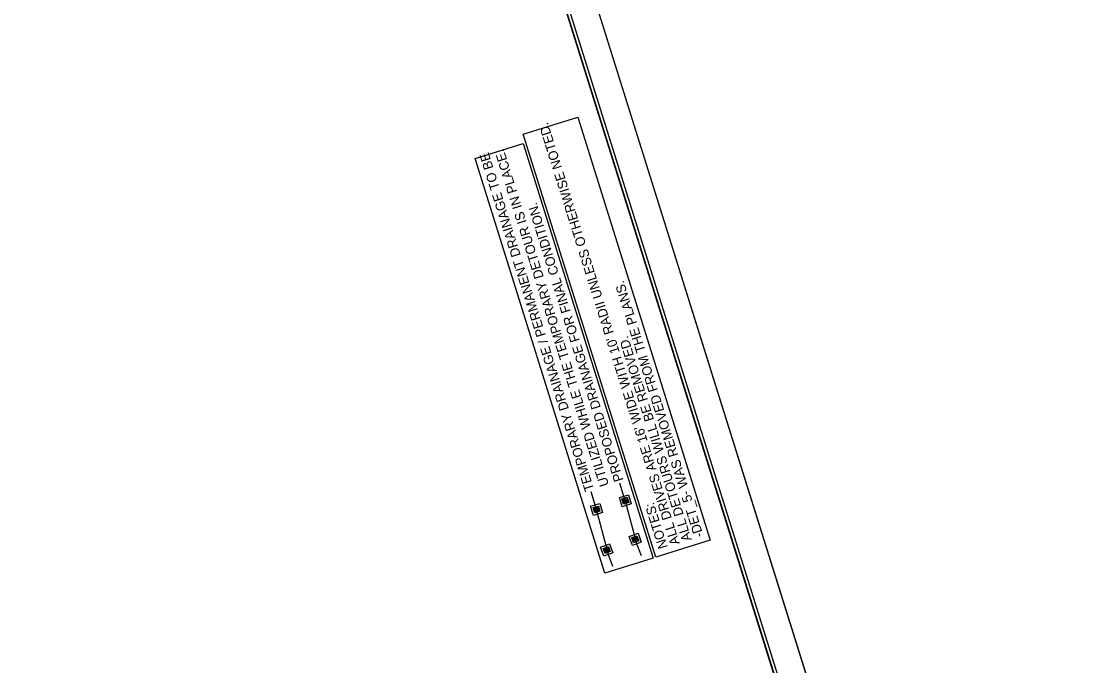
# Model space of a CAD drawing. Extents: x 473667 to 478950, y 494687 to 505998.
# Drawn here: x 474441 to 475215, y 505031 to 505503 of the extents above; entities that cross this region are included whole.
import ezdxf

# ---------------------------------------------------------------- set-up
doc = ezdxf.new("R2010")
doc.units = 0
for name, color, linetype in [('Old_Level_41', 7, 'Continuous'), ('Prop Drainage Structure CELL', 7, 'Continuous'), ('Prop DSN Text', 7, 'Continuous'), ('Prop Grid Mask', 7, 'Continuous'), ('Sheet Cutting Line CELL', 7, 'Continuous'), ('Sheet Data Field CELL', 7, 'Continuous'), ('Sheet Layout Plan Border', 7, 'Continuous'), ('Sheet Plan CELL', 7, 'Continuous'), ('Sheet Plan Layout CELL', 7, 'Continuous'), ('Sheet Plot Border Inside CELL', 7, 'Continuous'), ('Sheet Plot Border Outside CELL', 7, 'Continuous')]:
    doc.layers.add(name, color=color, linetype=linetype)

msp = doc.modelspace()

# ---------------------------------------------------------------- linework, layer by layer
at = {"layer": 'Old_Level_41'}
for p, q in [((474884.26, 505151.87), (474880.37, 505164.74)), ((474882.35, 505151.29), (474882.35, 505151.29)), ((474883.92, 505152.99), (474883.92, 505152.99)), ((474884.26, 505151.87), (474884.26, 505151.87)), ((474893.09, 505119.44), (474884.4, 505151.4)), ((474884.6, 505150.76), (474884.6, 505150.76)), ((474886.18, 505152.45), (474886.18, 505152.45)), ((474889.65, 505122.97), (474889.65, 505122.97)), ((474891.12, 505124.75), (474891.12, 505124.75)), ((474891.53, 505123.66), (474891.53, 505123.66)), ((474891.93, 505122.57), (474891.93, 505122.57)), ((474896.05, 505111.44), (474893.09, 505119.44)), ((474893.4, 505124.35), (474893.4, 505124.35))]:
    msp.add_line(p, q, dxfattribs=at)
for points in [[(474888.63, 505149.54), (474881.93, 505147.51), (474879.9, 505154.21), (474886.6, 505156.24)], [(474886.75, 505150.54), (474882.93, 505149.38), (474881.77, 505153.21), (474885.6, 505154.37)], [(474896.02, 505121.59), (474889.46, 505119.16), (474887.03, 505125.73), (474893.59, 505128.16)], [(474894.1, 505122.48), (474890.35, 505121.09), (474888.96, 505124.84), (474892.71, 505126.23)]]:
    msp.add_lwpolyline(points, close=True, dxfattribs=at)
for points in [[(474886.51, 505151.34), (474882.68, 505150.18), (474882.01, 505152.41), (474885.84, 505153.57), (474886.51, 505151.34)], [(474886.44, 505151.38), (474882.73, 505150.26), (474882.09, 505152.37), (474885.8, 505153.49), (474886.44, 505151.38)], [(474884.57, 505150.82), (474882.73, 505150.27), (474882.1, 505152.36), (474883.93, 505152.92), (474884.57, 505150.82)], [(474883.11, 505152.19), (474882.31, 505151.95), (474882.23, 505152.21), (474883.03, 505152.45), (474883.11, 505152.19)], [(474883.22, 505151.82), (474882.42, 505151.58), (474882.35, 505151.84), (474883.14, 505152.08), (474883.22, 505151.82)], [(474883.33, 505151.45), (474882.54, 505151.21), (474882.46, 505151.47), (474883.26, 505151.71), (474883.33, 505151.45)], [(474883.45, 505151.08), (474882.65, 505150.84), (474882.57, 505151.1), (474883.37, 505151.34), (474883.45, 505151.08)], [(474883.48, 505150.97), (474882.68, 505150.73), (474882.76, 505150.47), (474883.56, 505150.71), (474883.48, 505150.97)], [(474883.99, 505152.46), (474883.19, 505152.21), (474883.11, 505152.47), (474883.91, 505152.71), (474883.99, 505152.46)], [(474884.1, 505152.09), (474883.3, 505151.84), (474883.22, 505152.1), (474884.02, 505152.35), (474884.1, 505152.09)], [(474884.21, 505151.72), (474883.41, 505151.48), (474883.33, 505151.74), (474884.13, 505151.98), (474884.21, 505151.72)], [(474884.32, 505151.35), (474883.52, 505151.11), (474883.45, 505151.37), (474884.24, 505151.61), (474884.32, 505151.35)], [(474884.36, 505151.24), (474883.56, 505151), (474883.64, 505150.74), (474884.43, 505150.98), (474884.36, 505151.24)], [(474886.42, 505151.39), (474884.59, 505150.83), (474883.95, 505152.92), (474885.79, 505153.48), (474886.42, 505151.39)], [(474884.96, 505152.75), (474884.17, 505152.51), (474884.09, 505152.77), (474884.89, 505153.01), (474884.96, 505152.75)], [(474885.08, 505152.38), (474884.28, 505152.14), (474884.2, 505152.4), (474885, 505152.64), (474885.08, 505152.38)], [(474885.19, 505152.01), (474884.39, 505151.77), (474884.31, 505152.03), (474885.11, 505152.27), (474885.19, 505152.01)], [(474885.3, 505151.64), (474884.5, 505151.4), (474884.42, 505151.66), (474885.22, 505151.9), (474885.3, 505151.64)], [(474885.41, 505151.28), (474884.61, 505151.03), (474884.54, 505151.29), (474885.33, 505151.53), (474885.41, 505151.28)], [(474885.84, 505153.02), (474885.04, 505152.77), (474884.97, 505153.03), (474885.76, 505153.28), (474885.84, 505153.02)], [(474885.95, 505152.65), (474885.16, 505152.41), (474885.08, 505152.67), (474885.88, 505152.91), (474885.95, 505152.65)], [(474886.07, 505152.28), (474885.27, 505152.04), (474885.19, 505152.3), (474885.99, 505152.54), (474886.07, 505152.28)], [(474886.18, 505151.91), (474885.38, 505151.67), (474885.3, 505151.93), (474886.1, 505152.17), (474886.18, 505151.91)], [(474886.29, 505151.54), (474885.49, 505151.3), (474885.41, 505151.56), (474886.21, 505151.8), (474886.29, 505151.54)], [(474893.81, 505123.26), (474890.06, 505121.87), (474889.25, 505124.06), (474893, 505125.45), (474893.81, 505123.26)], [(474893.73, 505123.3), (474890.09, 505121.95), (474889.33, 505124.02), (474892.96, 505125.37), (474893.73, 505123.3)], [(474891.9, 505122.63), (474890.1, 505121.96), (474889.34, 505124.02), (474891.14, 505124.68), (474891.9, 505122.63)], [(474890.36, 505123.9), (474889.58, 505123.62), (474889.48, 505123.87), (474890.27, 505124.16), (474890.36, 505123.9)], [(474890.49, 505123.54), (474889.71, 505123.25), (474889.62, 505123.51), (474890.4, 505123.8), (474890.49, 505123.54)], [(474890.63, 505123.18), (474889.85, 505122.89), (474889.75, 505123.15), (474890.53, 505123.44), (474890.63, 505123.18)], [(474890.76, 505122.82), (474889.98, 505122.53), (474889.89, 505122.78), (474890.67, 505123.07), (474890.76, 505122.82)], [(474890.8, 505122.71), (474890.02, 505122.42), (474890.11, 505122.17), (474890.89, 505122.46), (474890.8, 505122.71)], [(474891.22, 505124.22), (474890.44, 505123.93), (474890.34, 505124.19), (474891.12, 505124.48), (474891.22, 505124.22)], [(474891.35, 505123.86), (474890.57, 505123.57), (474890.48, 505123.83), (474891.26, 505124.12), (474891.35, 505123.86)], [(474891.49, 505123.5), (474890.71, 505123.21), (474890.61, 505123.46), (474891.39, 505123.75), (474891.49, 505123.5)], [(474891.62, 505123.14), (474890.84, 505122.85), (474890.74, 505123.1), (474891.53, 505123.39), (474891.62, 505123.14)], [(474891.66, 505123.03), (474890.88, 505122.74), (474890.97, 505122.49), (474891.75, 505122.78), (474891.66, 505123.03)], [(474893.71, 505123.3), (474891.92, 505122.64), (474891.16, 505124.69), (474892.95, 505125.35), (474893.71, 505123.3)], [(474892.18, 505124.58), (474891.39, 505124.29), (474891.3, 505124.54), (474892.08, 505124.83), (474892.18, 505124.58)], [(474892.31, 505124.22), (474891.53, 505123.93), (474891.43, 505124.18), (474892.22, 505124.47), (474892.31, 505124.22)], [(474892.44, 505123.85), (474891.66, 505123.57), (474891.57, 505123.82), (474892.35, 505124.11), (474892.44, 505123.85)], [(474892.58, 505123.49), (474891.8, 505123.2), (474891.7, 505123.46), (474892.48, 505123.75), (474892.58, 505123.49)], [(474892.71, 505123.13), (474891.93, 505122.84), (474891.84, 505123.1), (474892.62, 505123.39), (474892.71, 505123.13)], [(474893.04, 505124.9), (474892.25, 505124.61), (474892.16, 505124.86), (474892.94, 505125.15), (474893.04, 505124.9)], [(474893.17, 505124.53), (474892.39, 505124.24), (474892.29, 505124.5), (474893.08, 505124.79), (474893.17, 505124.53)], [(474893.3, 505124.17), (474892.52, 505123.88), (474892.43, 505124.14), (474893.21, 505124.43), (474893.3, 505124.17)], [(474893.44, 505123.81), (474892.66, 505123.52), (474892.56, 505123.78), (474893.34, 505124.07), (474893.44, 505123.81)], [(474893.57, 505123.45), (474892.79, 505123.16), (474892.7, 505123.41), (474893.48, 505123.7), (474893.57, 505123.45)]]:
    msp.add_lwpolyline(points, dxfattribs=at)
at = {"layer": 'Prop Drainage Structure CELL'}
for p, q in [((474863.19, 505145.5), (474859.3, 505158.37)), ((474861.27, 505144.93), (474861.27, 505144.93)), ((474862.85, 505146.62), (474862.85, 505146.62)), ((474863.19, 505145.5), (474863.19, 505145.5)), ((474872.26, 505111.55), (474863.22, 505145.37)), ((474863.53, 505144.39), (474863.53, 505144.39)), ((474865.1, 505146.08), (474865.1, 505146.08)), ((474868.83, 505115.08), (474868.83, 505115.08)), ((474870.3, 505116.87), (474870.3, 505116.87)), ((474870.7, 505115.77), (474870.7, 505115.77)), ((474871.11, 505114.68), (474871.11, 505114.68)), ((474872.58, 505116.47), (474872.58, 505116.47)), ((474875.23, 505103.55), (474872.26, 505111.55))]:
    msp.add_line(p, q, dxfattribs=at)
for points in [[(474867.55, 505143.17), (474860.85, 505141.14), (474858.82, 505147.84), (474865.52, 505149.87)], [(474865.68, 505144.17), (474861.85, 505143.01), (474860.69, 505146.84), (474864.52, 505148)], [(474875.2, 505113.7), (474868.63, 505111.27), (474866.2, 505117.84), (474872.77, 505120.27)], [(474873.27, 505114.59), (474869.52, 505113.2), (474868.13, 505116.95), (474871.88, 505118.34)]]:
    msp.add_lwpolyline(points, close=True, dxfattribs=at)
for points in [[(474865.44, 505144.97), (474861.61, 505143.81), (474860.94, 505146.04), (474864.76, 505147.2), (474865.44, 505144.97)], [(474865.36, 505145.01), (474861.65, 505143.89), (474861.01, 505146), (474864.72, 505147.12), (474865.36, 505145.01)], [(474863.49, 505144.45), (474861.66, 505143.9), (474861.03, 505145.99), (474862.86, 505146.55), (474863.49, 505144.45)], [(474862.04, 505145.82), (474861.24, 505145.58), (474861.16, 505145.84), (474861.96, 505146.08), (474862.04, 505145.82)], [(474862.15, 505145.45), (474861.35, 505145.21), (474861.27, 505145.47), (474862.07, 505145.71), (474862.15, 505145.45)], [(474862.26, 505145.08), (474861.46, 505144.84), (474861.38, 505145.1), (474862.18, 505145.34), (474862.26, 505145.08)], [(474862.37, 505144.71), (474861.57, 505144.47), (474861.5, 505144.73), (474862.29, 505144.97), (474862.37, 505144.71)], [(474862.4, 505144.6), (474861.61, 505144.36), (474861.69, 505144.1), (474862.48, 505144.34), (474862.4, 505144.6)], [(474862.91, 505146.09), (474862.12, 505145.84), (474862.04, 505146.1), (474862.84, 505146.34), (474862.91, 505146.09)], [(474863.03, 505145.72), (474862.23, 505145.48), (474862.15, 505145.73), (474862.95, 505145.98), (474863.03, 505145.72)], [(474863.14, 505145.35), (474862.34, 505145.11), (474862.26, 505145.37), (474863.06, 505145.61), (474863.14, 505145.35)], [(474863.25, 505144.98), (474862.45, 505144.74), (474862.37, 505145), (474863.17, 505145.24), (474863.25, 505144.98)], [(474863.28, 505144.87), (474862.48, 505144.63), (474862.56, 505144.37), (474863.36, 505144.61), (474863.28, 505144.87)], [(474865.35, 505145.02), (474863.51, 505144.46), (474862.88, 505146.55), (474864.72, 505147.11), (474865.35, 505145.02)], [(474863.89, 505146.38), (474863.09, 505146.14), (474863.01, 505146.4), (474863.81, 505146.64), (474863.89, 505146.38)], [(474864, 505146.01), (474863.2, 505145.77), (474863.13, 505146.03), (474863.92, 505146.27), (474864, 505146.01)], [(474864.11, 505145.64), (474863.32, 505145.4), (474863.24, 505145.66), (474864.04, 505145.9), (474864.11, 505145.64)], [(474864.23, 505145.27), (474863.43, 505145.03), (474863.35, 505145.29), (474864.15, 505145.53), (474864.23, 505145.27)], [(474864.34, 505144.91), (474863.54, 505144.66), (474863.46, 505144.92), (474864.26, 505145.16), (474864.34, 505144.91)], [(474864.77, 505146.65), (474863.97, 505146.41), (474863.89, 505146.66), (474864.69, 505146.91), (474864.77, 505146.65)], [(474864.88, 505146.28), (474864.08, 505146.04), (474864, 505146.3), (474864.8, 505146.54), (474864.88, 505146.28)], [(474864.99, 505145.91), (474864.19, 505145.67), (474864.12, 505145.93), (474864.91, 505146.17), (474864.99, 505145.91)], [(474865.1, 505145.54), (474864.31, 505145.3), (474864.23, 505145.56), (474865.02, 505145.8), (474865.1, 505145.54)], [(474865.21, 505145.17), (474864.42, 505144.93), (474864.34, 505145.19), (474865.14, 505145.43), (474865.21, 505145.17)], [(474872.98, 505115.37), (474869.23, 505113.98), (474868.42, 505116.17), (474872.17, 505117.56), (474872.98, 505115.37)], [(474872.9, 505115.41), (474869.27, 505114.06), (474868.5, 505116.13), (474872.14, 505117.48), (474872.9, 505115.41)], [(474871.07, 505114.74), (474869.27, 505114.08), (474868.51, 505116.13), (474870.31, 505116.79), (474871.07, 505114.74)], [(474869.53, 505116.02), (474868.75, 505115.73), (474868.66, 505115.98), (474869.44, 505116.27), (474869.53, 505116.02)], [(474869.67, 505115.66), (474868.89, 505115.37), (474868.79, 505115.62), (474869.57, 505115.91), (474869.67, 505115.66)], [(474869.8, 505115.29), (474869.02, 505115), (474868.93, 505115.26), (474869.71, 505115.55), (474869.8, 505115.29)], [(474869.93, 505114.93), (474869.15, 505114.64), (474869.06, 505114.9), (474869.84, 505115.19), (474869.93, 505114.93)], [(474869.97, 505114.83), (474869.19, 505114.54), (474869.29, 505114.28), (474870.07, 505114.57), (474869.97, 505114.83)], [(474870.39, 505116.34), (474869.61, 505116.05), (474869.52, 505116.3), (474870.3, 505116.59), (474870.39, 505116.34)], [(474870.53, 505115.97), (474869.75, 505115.68), (474869.65, 505115.94), (474870.43, 505116.23), (474870.53, 505115.97)], [(474870.66, 505115.61), (474869.88, 505115.32), (474869.79, 505115.58), (474870.57, 505115.87), (474870.66, 505115.61)], [(474870.79, 505115.25), (474870.01, 505114.96), (474869.92, 505115.22), (474870.7, 505115.5), (474870.79, 505115.25)], [(474870.83, 505115.14), (474870.05, 505114.85), (474870.15, 505114.6), (474870.93, 505114.89), (474870.83, 505115.14)], [(474872.89, 505115.42), (474871.09, 505114.75), (474870.33, 505116.8), (474872.13, 505117.47), (474872.89, 505115.42)], [(474871.35, 505116.69), (474870.57, 505116.4), (474870.47, 505116.65), (474871.26, 505116.94), (474871.35, 505116.69)], [(474871.48, 505116.33), (474870.7, 505116.04), (474870.61, 505116.29), (474871.39, 505116.58), (474871.48, 505116.33)], [(474871.62, 505115.97), (474870.84, 505115.68), (474870.74, 505115.93), (474871.52, 505116.22), (474871.62, 505115.97)], [(474871.75, 505115.61), (474870.97, 505115.32), (474870.88, 505115.57), (474871.66, 505115.86), (474871.75, 505115.61)], [(474871.89, 505115.24), (474871.1, 505114.95), (474871.01, 505115.21), (474871.79, 505115.5), (474871.89, 505115.24)], [(474872.21, 505117.01), (474871.43, 505116.72), (474871.33, 505116.97), (474872.12, 505117.26), (474872.21, 505117.01)], [(474872.34, 505116.65), (474871.56, 505116.36), (474871.47, 505116.61), (474872.25, 505116.9), (474872.34, 505116.65)], [(474872.48, 505116.28), (474871.7, 505116), (474871.6, 505116.25), (474872.38, 505116.54), (474872.48, 505116.28)], [(474872.61, 505115.92), (474871.83, 505115.63), (474871.74, 505115.89), (474872.52, 505116.18), (474872.61, 505115.92)], [(474872.75, 505115.56), (474871.96, 505115.27), (474871.87, 505115.53), (474872.65, 505115.82), (474872.75, 505115.56)]]:
    msp.add_lwpolyline(points, dxfattribs=at)
at = {"layer": 'Prop Grid Mask'}
for points in [[(474906.56, 505110.55), (474809.46, 505420.49), (474849.39, 505433), (474946.49, 505123.06)], [(474869.33, 505098.68), (474774.09, 505402.68), (474809.5, 505413.78), (474904.74, 505109.78)]]:
    msp.add_lwpolyline(points, close=True, dxfattribs=at)
at = {"layer": 'Sheet Cutting Line CELL'}
msp.add_line((475215.38, 504391.22), (474712.1, 505997.73), dxfattribs=at)
at = {"layer": 'Sheet Layout Plan Border'}
msp.add_lwpolyline([(474406.84, 504597.01), (474903.65, 504485.25), (475129.18, 504591.08), (474710.64, 505927.06), (474746.68, 505812.01), (474670.33, 505788.09), (474619.34, 505950.85), (473859.33, 505712.76), (473919.13, 505521.87), (473753.52, 505469.97), (474127.2, 504277.17)], close=True, dxfattribs=at)
at = {"layer": 'Sheet Plan CELL'}
for points in [[(473693.71, 505660.9), (474142.15, 504229.46), (475144.13, 504543.36), (474695.69, 505974.78)], [(475144.13, 504543.36), (474142.18, 504229.44), (473753.51, 505469.97), (473896.7, 505514.84), (473836.91, 505705.74), (474695.69, 505974.78)]]:
    msp.add_lwpolyline(points, close=True, dxfattribs=at)
at = {"layer": 'Sheet Plan Layout CELL'}
msp.add_lwpolyline([(474142.18, 504229.44), (475144.13, 504543.36), (474695.7, 505974.76), (473895.53, 505724.09), (473967.06, 505495.78), (473765.24, 505432.55)], close=True, dxfattribs=at)
at = {"layer": 'Sheet Plot Border Inside CELL'}
msp.add_lwpolyline([(475192.41, 504397.64), (474694.35, 505987.44), (473687.6, 505672.06), (474185.66, 504082.25)], close=True, dxfattribs=at)
at = {"layer": 'Sheet Plot Border Outside CELL'}
msp.add_lwpolyline([(475215.38, 504391.22), (474712.1, 505997.73), (473667.17, 505670.37), (474170.46, 504063.86)], close=True, dxfattribs=at)

# ---------------------------------------------------------------- texts
at = {"layer": 'Prop DSN Text'}
for s, p in [("ALL DRIVES ARE 16' WIDE WITH 10' RADII UNLESS OTHERWISE NOTED. ", (474924.22, 505120.62)), ('-DET_5- WAS REMOVED FROM THE PLANS. ', (474941.73, 505126.11)), ('ALL DETOURS WILL BE REMOVED. ', (474932.97, 505123.37)), ('NOTES: ', (474915.46, 505117.88))]:
    msp.add_text(s, height=7, rotation=107.39476, dxfattribs=at).set_placement(p)
at = {"layer": 'Sheet Data Field CELL'}
for s, p in [('TEMPORARY DRAINAGE / PERMANENT DRAINAGE TO BE ', (474861.51, 505160.04)), ('UTILIZED WHILE THE TEMPORARY DETOUR IS IN PLACE.', (474872.37, 505163.44)), ('PROPOSED DRAINAGE FOR FINAL CONDITION.', (474883.04, 505167.03))]:
    msp.add_text(s, height=7, rotation=107.39476, dxfattribs=at).set_placement(p)

doc.saveas('drawing.dxf')
